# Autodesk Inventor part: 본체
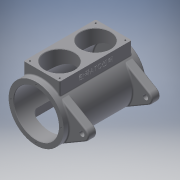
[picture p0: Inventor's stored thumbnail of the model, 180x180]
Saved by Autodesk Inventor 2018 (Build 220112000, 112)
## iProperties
Created: 2016-11
Part Number: 본체
Material: 알루미늄 6061
Document SubType Name: Modeling
Designer: mduedu
Density: 2.71 g/cm^3
Appearance: 기본값
Mass: 2578.28 g
Surface Area: 1746.6 cm^2
Volume: 951.394 cm^3
Author: mduedu
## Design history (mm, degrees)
sketch "스케치1"
  geometry: C1 r 65 at (0, 0); 1 further point
  constraints: 1 centre point, 1 coincident
  dimensions: "d119" = 130 diameter of C1
extrude "돌출1" new body sketch "스케치1" distance "d3" = 98; taper "d4" = 0 deg; dims "d132" = 97, "d133" = 0
feature "쉘1" dims "d120" = 12, "d134" = 8
node "작업 평면2"
sketch "스케치13"
  geometry: L1 (42.5, 85)-(-42.5, 85); L2 (-42.5, 85)-(-42.5, -85); L3 (-42.5, -85)-(42.5, -85); L4 (42.5, -85)-(42.5, 85); 2 further points
  constraints: 8 end point, 2 parallel, 1 horizontal, 1 midpoint, 1 perpendicular, 1 vertical alignment
  dimensions: "d122" = 170 distance of L1.end L2.end; "d124" = 85 distance of L2.end L3.end; "d125" = 85 distance from line of point (0, 0) L1 (= 0.5 x d122)
extrude "돌출11" join sketch "스케치13" stored distance "d126" = 10; taper "d127" = 0 deg
sketch "스케치14"
  geometry: L1 (65, 97)-(-65, 97) reference; C1 r 35 at (0, 42.5); 1 further point
  constraints: 1 centre point, 1 vertical alignment
  dimensions: "d128" = 70 diameter of C1; "d129" = 54.5 distance from line of C1.centre L1
extrude "돌출12" cut sketch "스케치14" stored distance "d130" = 10; taper "d131" = 0 deg
sketch "스케치15"
  geometry: C1 r 53 at (0, 0) reference; 1 further point
extrude "돌출13" cut sketch "스케치15" stored distance "d135" = 10; taper "d136" = 0 deg
chamfer "모따기1" distance "d54" = 1; stored, may be unused: second distance "d55" = 2, angle "d56" = 45 deg
sketch "스케치8"
  geometry: C1 r 23 at (0, 0); C2 r 65 at (0, 0) reference; 1 further point
  constraints: 1 centre point, 1 concentric
  dimensions: "d57" = 46 diameter of C1
extrude "돌출8" join sketch "스케치8" distance "d58" = 14; taper "d59" = 0 deg
feature "면 기울기1" dims angle "d202" = 10 deg
hole "구멍3" diameter "d62" = 24; stored, may be unused: countersink angle "d66" = 90 deg, drill point angle "d68" = 0 deg; dims "d63" = 6, "d64" = 28, "d65" = 8, "d67" = 14, "d169" = 10, "d170" = 10
fillet "모깎기11" dims "d69" = 3
fillet "모깎기12" dims "d70" = 3
fillet "모깎기13" dims "d71" = 0.3
chamfer "모따기2" distance "d72" = 1; stored, may be unused: second distance "d73" = 2, angle "d74" = 45 deg
node "작업 평면3"
sketch "스케치16"
  geometry: L1 (-42.5, -80)-(52.5, -80); L2 (-42.5, -80)-(24.675, -12.825); L3 (-42.5, -80)-(24.675, -147.175); L4 (3.462, -34.038)-(60.057, -67.042); L5 (3.462, -125.962)-(60.057, -92.958); A1 r 65 centre (-42.5, -80) between (3.462, -34.038) and (3.462, -125.962) reference; A2 r 65 centre (-42.5, -80) between (3.462, -125.962) and (3.462, -34.038); A3 r 95 centre (-42.5, -80) between (52.5, -80) and (24.675, -147.175); A4 r 15 centre (52.5, -80) between (60.057, -67.042) and (60.057, -92.958); 1 further point
  constraints: 10 end point, 9 point on circle, 3 centre point, 3 coincident, 2 point on line, 2 tangent, 1 horizontal
  dimensions: "d140" = 45 deg angle of L3 L1; "d141" = 45 deg angle of L2 L1; "d194" = 30 radial gap between concentric circles of A3 A1; "d195" = 30 diameter of A4
extrude "돌출14" join sketch "스케치16" distance "d143" = 20; taper "d144" = 0 deg
fillet "모깎기25" dims "d196" = 3
fillet "모깎기26" dims "d197" = 3
sketch "스케치22"
  geometry: C1 r 6 at (52.5, -80); A1 r 15 centre (52.5, -80) between (60.057, -92.958) and (60.057, -67.042) reference; 1 further point
  constraints: 1 centre point, 1 coincident
  dimensions: "d198" = 12 diameter of C1
extrude "돌출17" cut sketch "스케치22" extent not by distance; stored distance "d200" = 10; taper "d201" = 0 deg
fillet "모깎기20" dims "d159" = 3
fillet "모깎기21" dims "d160" = 3
fillet "모깎기22" dims "d161" = 3
node "작업 평면4"
sketch "스케치18"
  geometry: L1 (-42.5, 65)-(42.5, 65); L2 (42.5, 65)-(42.5, -65); L3 (42.5, -65)-(-42.5, -65); L4 (-42.5, -65)-(-42.5, 65); 2 further points
  constraints: 8 end point, 2 parallel, 1 horizontal, 1 midpoint, 1 perpendicular, 1 vertical alignment
  dimensions: "d162" = 130 distance of L1.end L2.end; "d164" = 85 distance of L2.end L3.end; "d165" = 65 distance from line of point (0, 0) L1 (= 0.5 x d162)
extrude "돌출16" cut sketch "스케치18" stored distance "d166" = 15; taper "d167" = 0 deg
fillet "모깎기23" dims "d168" = 10
fillet "모깎기24" dims "d173" = 3
sketch "스케치19"
  geometry: 4 further points
  constraints: 4 other
hole "구멍6" sketch "스케치19" at (0, -59), (59, 0), (-59, 0), (0, 59) diameter "d174" = 3.242; stored, may be unused: countersink angle "d178" = 90 deg, drill point angle "d180" = 120 deg; dims "d175" = 7, "d176" = 4, "d177" = 2, "d179" = 9
sketch "스케치20"
  geometry: L1 (35, -77.5)-(-35, -77.5); L2 (-35, -77.5)-(-35, -7.5); L3 (-35, -7.5)-(35, -7.5); L4 (35, -7.5)-(35, -77.5); L5 (35, -77.5)-(-35, -7.5); L6 (-35, -77.5)-(35, -7.5); C1 r 36 at (0, -42.5) reference; 3 further points
  constraints: 12 end point, 2 coincident, 2 midpoint, 2 parallel, 1 horizontal, 1 perpendicular
  dimensions: "d181" = 70 distance of L2.end L3.end; "d182" = 70 distance of L1.end L2.end
hole "구멍7" sketch "스케치20" at (-35, -77.5), (35, -77.5) diameter "d183" = 3.242; stored, may be unused: countersink angle "d187" = 90 deg, drill point angle "d189" = 118 deg; dims "d184" = 7, "d185" = 4, "d186" = 2, "d188" = 9
sketch "스케치21"
  geometry: L1 (164, 0)-(0, 0) reference; L2 (-3, 0)-(-3, -24.649) reference; 3 further points
  constraints: 1 midpoint, 1 vertical alignment, 1 other
  dimensions: "d190" = 15 distance from line of point (82, -15) L1; "d191" = 85 distance from line of point (82, 0) L2 (derived)
feature "엠보싱2" sketch "스케치21" dims "d119" = 130, "d192" = 0.5, "d193" = 0
node "솔리드1"
mirror "대칭5"
mirror "대칭6"
mirror "대칭7"
